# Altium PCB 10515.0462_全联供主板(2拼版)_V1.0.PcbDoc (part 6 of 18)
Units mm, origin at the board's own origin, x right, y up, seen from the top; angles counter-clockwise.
Board outline 282 x 198 mm, 2 copper layers (Top Layer, Bottom Layer); 716 components, 0 nets, 2364 pads, 1800 vias.
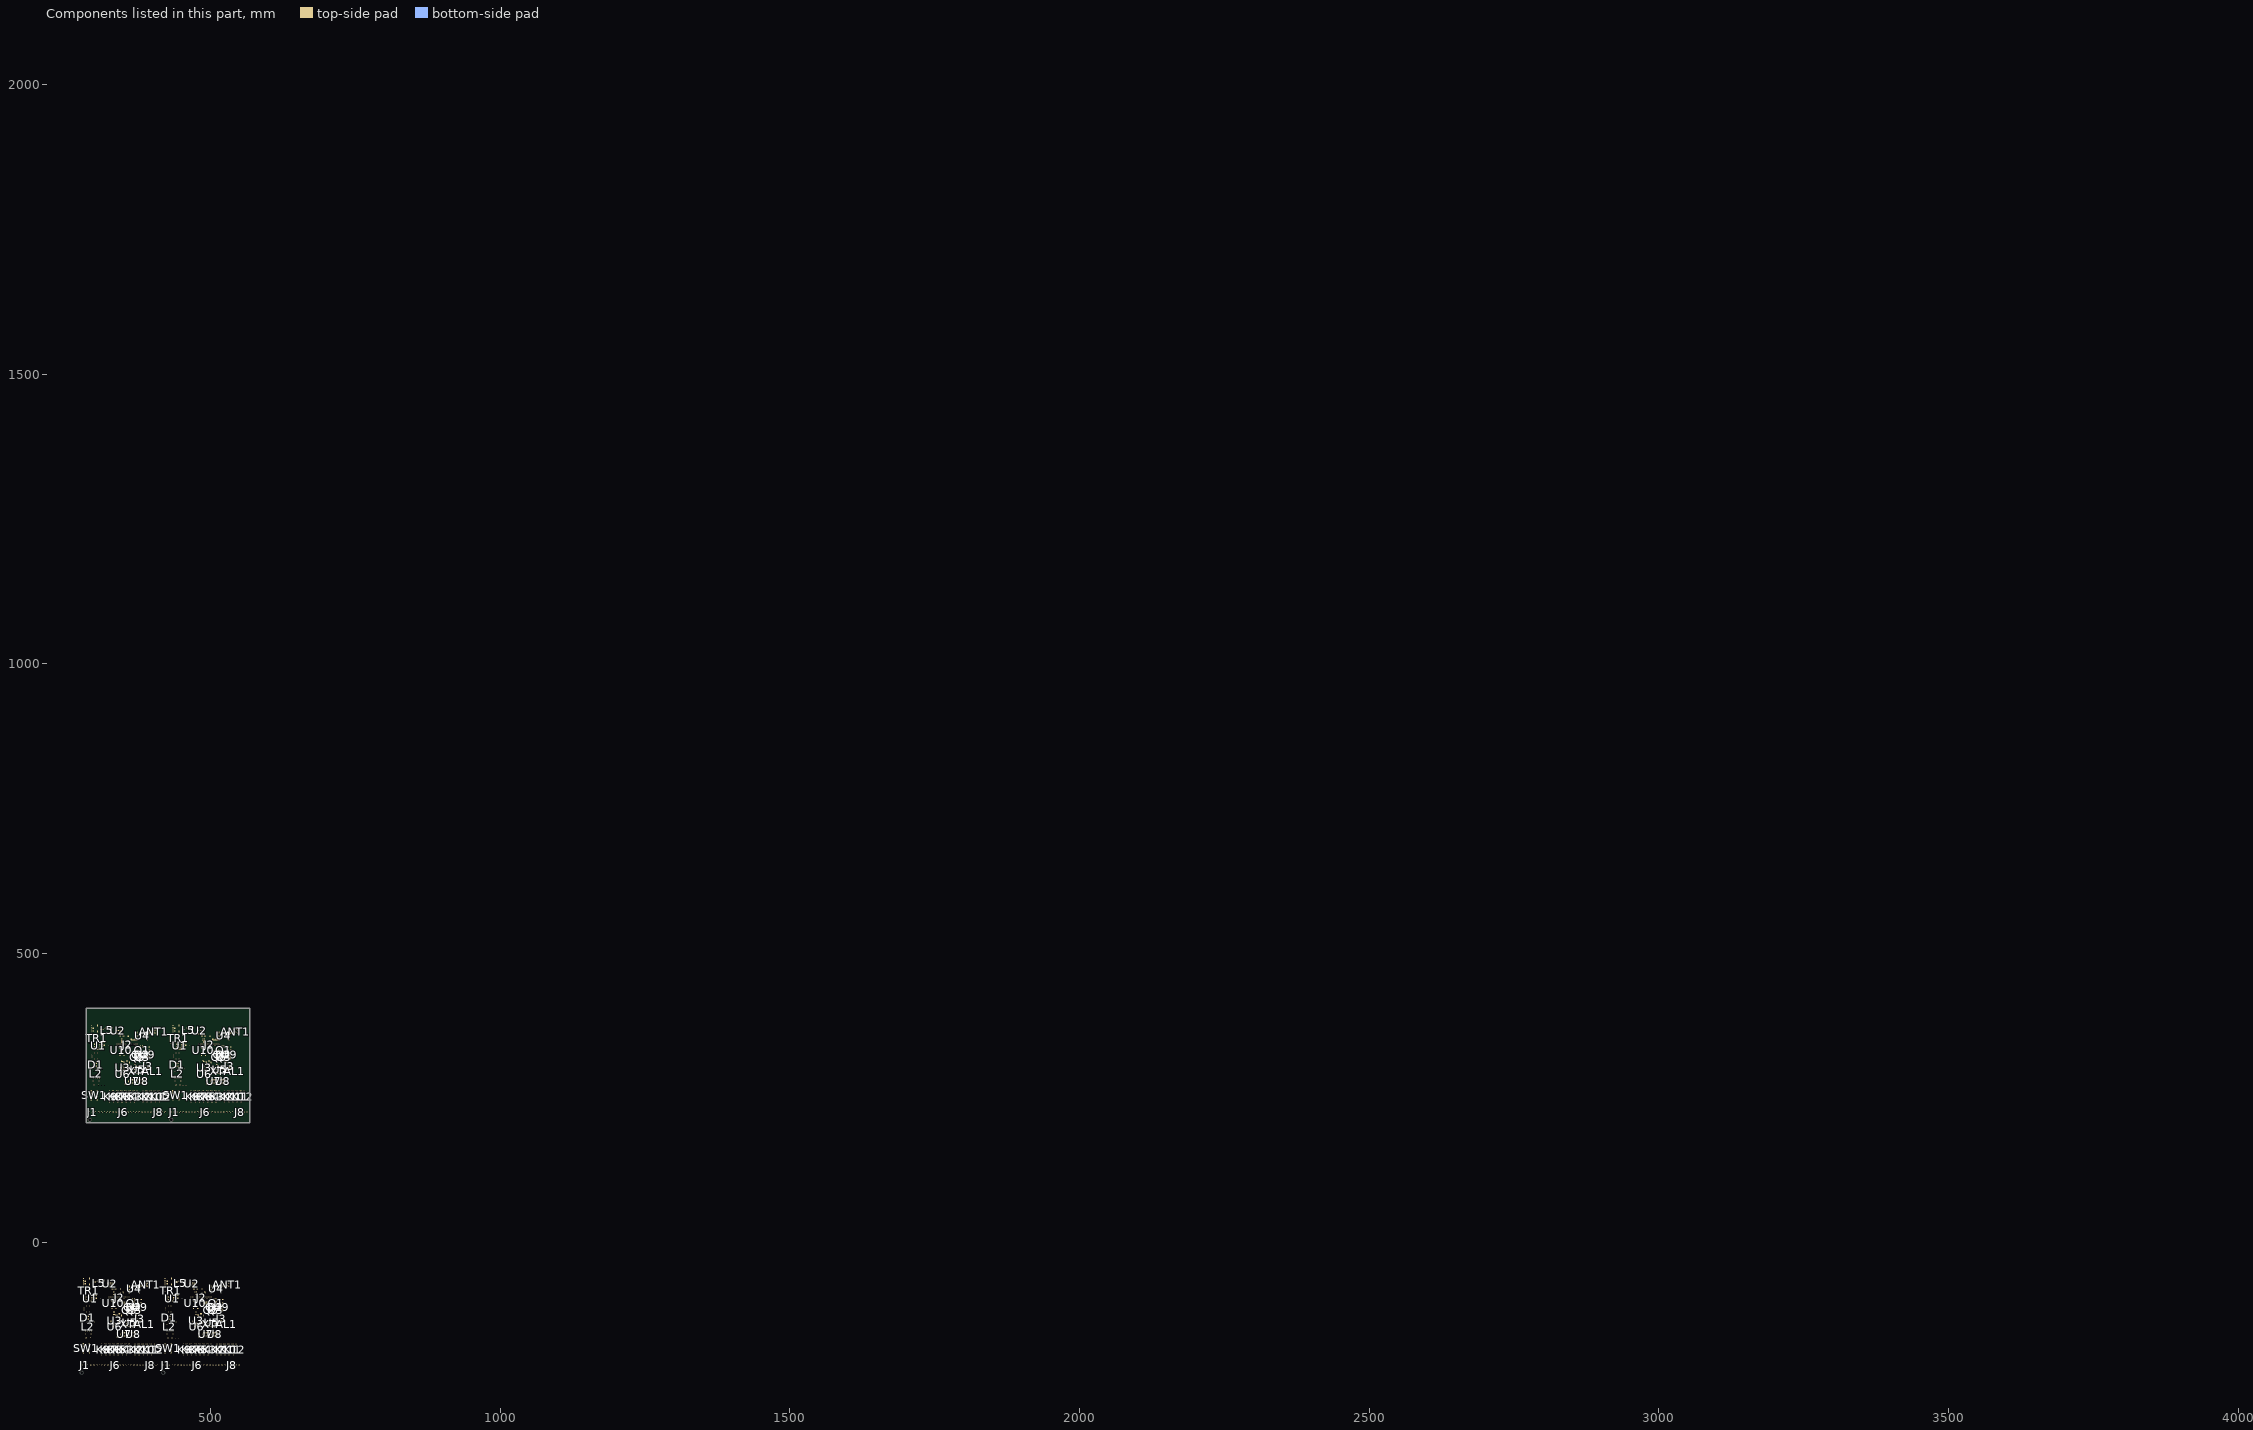
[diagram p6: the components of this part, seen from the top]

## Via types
v1: diameter 0.7, hole 0.4, Top Layer to Bottom Layer, tented both sides, 1800 vias

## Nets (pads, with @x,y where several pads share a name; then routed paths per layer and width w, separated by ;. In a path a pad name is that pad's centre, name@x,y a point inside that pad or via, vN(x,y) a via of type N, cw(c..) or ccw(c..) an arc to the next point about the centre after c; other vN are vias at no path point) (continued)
copper on no net: (continued)
  Top Layer w0.45: 289.059,-97.823 289.059,-97.562 ; 289.059,-95.283 289.059,-94.895 ; 290.415,-99.768 ccw(c290.263,-99.478) 290.59,-99.478 ; 290.59,-100.099 290.59,-99.478 ; 290.677,-100.099 cw(c292.386,-100.099) 291.178,-98.891 ; 290.765,-99.768 cw(c290.917,-99.478) 290.59,-99.478 ; 291.127,-100.099 cw(c293.923,-100.099) 291.946,-98.123 ; 292.576,-99.834 ccw(c291.851,-99.11) 292.876,-99.11 ; 292.876,-99.972 292.876,-96.049 293.642,-95.283 295.155,-95.283 297.071,-95.283 297.448,-94.906 297.448,-93.763 298.464,-92.747 ; 292.876,-99.279 ccw(c293.662,-99.279) 293.106,-99.834 ; 295.155,-97.823 298.976,-97.823 ; 295.155,-94.013 292.753,-94.013 291.987,-94.779 291.987,-98.081 290.59,-99.478 ; 295.375,-90.056 ccw(c296.32,-89.112) 296.32,-90.447 ; 295.693,-89.738 ccw(c297.406,-88.025) 297.406,-90.447 ; 296.012,-89.42 ccw(c298.492,-86.939) 298.492,-90.447 ; 296.226,-90.447 299.48,-90.447 302.209,-90.447 ; 297.196,-97.823 ccw(c297.196,-95.198) 299.053,-97.054 ; 298.283,-97.823 ccw(c298.283,-96.284) 299.371,-97.372 ; 299.042,-93.001 ccw(c298.464,-93.532) 298.464,-92.747 ; 299.042,-92.494 cw(c298.464,-91.963) 298.464,-92.747 ; 299.053,-90.713 ccw(c298.413,-91.353) 298.413,-90.447 ccw(c298.413,-89.542) 299.053,-90.182 ; 299.48,-92.747 298.464,-92.747 ; 299.632,-90.447 ccw(c299.632,-87.582) 301.658,-89.608 ; 299.907,-90.713 cw(c300.547,-91.353) 300.547,-90.447 cw(c300.547,-89.542) 299.907,-90.182 ; 300.356,-90.447 cw(c300.356,-92.29) 301.658,-90.987 ; 300.494,-90.447 cw(c300.494,-92.639) 302.119,-91.169 ; 300.719,-90.447 ccw(c300.719,-88.668) 301.977,-89.926 ; 301.047,-90.447 ccw(c301.047,-89.355) 301.819,-90.128 ; v1(301.986,-81.687) 303.002,-82.703 304.78,-82.703 ; v1@302.191,-81.892 ccw(c302.621,-81.462) v1@302.621,-82.07 ; 302.494,-80.544 301.859,-80.544 301.605,-80.798 301.605,-82.068 302.24,-82.703 304.78,-82.703 ; 302.688,338.772 302.688,339.033 ; 302.688,341.312 302.688,341.7 ; v1@302.746,-82.195 ccw(c303.354,-82.195) 302.924,-82.625 ; 304.044,336.828 ccw(c303.892,337.117) 304.219,337.117 ccw(c304.545,337.117) 304.393,336.828 ; 304.219,336.496 304.219,337.117 305.616,338.514 305.616,341.816 306.382,342.582 308.784,342.582 ; 304.306,336.496 cw(c306.015,336.496) 304.806,337.705 ; 304.756,336.496 cw(c307.551,336.496) 305.575,338.473 ; 306.205,336.761 ccw(c305.48,337.486) 306.505,337.486 ; 306.505,336.623 306.505,340.546 307.271,341.312 308.784,341.312 310.7,341.312 311.077,341.689 311.077,342.832 312.093,343.848 ; 306.505,337.317 ccw(c307.291,337.317) 306.735,336.761 ; 308.784,338.772 312.605,338.772 ; 309.004,346.539 ccw(c309.948,347.484) 309.948,346.148 ; 309.322,346.857 ccw(c311.035,348.57) 311.035,346.148 ; 309.64,347.176 ccw(c312.121,349.656) 312.121,346.148 ; 309.855,346.148 313.109,346.148 315.838,346.148 ; 310.825,338.772 ccw(c310.825,341.398) 312.682,339.541 ; 311.194,-173.925 ccw(c310.041,-172.772) 311.671,-172.772 ccw(c313.301,-172.772) 312.148,-173.925 ; 311.671,-174.752 311.671,-172.123 314.72,-169.074 346.978,-169.074 347.613,-168.439 347.613,-166.153 347.613,-160.438 ; 311.912,338.772 ccw(c311.912,340.311) 313,339.223 ; 312.671,343.594 ccw(c312.093,343.063) 312.093,343.848 ; 312.671,344.102 cw(c312.093,344.633) 312.093,343.848 ; 312.682,345.883 ccw(c312.041,345.243) 312.041,346.148 ccw(c312.041,347.053) 312.682,346.413 ; 313.109,343.848 312.093,343.848 ; 313.261,346.148 ccw(c313.261,349.013) 315.287,346.987 ; 313.536,345.883 cw(c314.176,345.243) 314.176,346.148 cw(c314.176,347.053) 313.536,346.413 ; 313.985,346.148 cw(c313.985,344.306) 315.287,345.608 ; 314.123,346.148 cw(c314.123,343.956) 315.748,345.426 ; 314.348,346.148 ccw(c314.348,347.927) 315.605,346.669 ; 314.676,346.148 ccw(c314.676,347.24) 315.448,346.468 ; v1(315.615,354.908) 316.631,353.892 318.409,353.892 ; v1@315.82,354.704 ccw(c316.25,355.134) v1@316.25,354.525 ; 316.083,-83.846 314.94,-82.703 304.78,-82.703 ; 316.123,356.051 315.488,356.051 315.234,355.797 315.234,354.527 315.869,353.892 318.409,353.892 ; v1@316.375,354.4 ccw(c316.983,354.4) 316.553,353.97 ; 318.379,-173.925 ccw(c317.227,-172.772) 318.856,-172.772 ccw(c320.486,-172.772) 319.334,-173.925 ; 318.856,-174.752 318.856,-172.05 321.1,-169.806 347.897,-169.806 348.883,-168.82 348.883,-166.534 348.883,-160.438 ; 320.995,-71.781 321.544,-71.781 ; 321.29,-72.035 321.544,-71.781 ; 321.544,-71.831 cw(c322.391,-71.831) 321.932,-71.119 ; 321.63,-67.78 cw(c321.139,-68.272) 321.834,-68.272 ; 321.706,-69.111 ccw(c321.396,-68.802) 321.834,-68.802 ccw(c322.272,-68.802) 321.962,-69.111 ; 321.834,-71.781 321.925,-71.781 ; 321.834,-67.666 321.834,-69.278 322.198,-69.642 324.458,-69.642 ; 321.847,-70.942 324.458,-70.942 ; 321.962,-70.801 ccw(c322.304,-70.459) 322.304,-70.942 ; 321.962,-69.188 ccw(c323.06,-68.09) 323.06,-69.642 ; 321.979,-70.857 ccw(c322.814,-70.225) v1@322.814,-71.273 ; 322.772,-70.942 ccw(c322.772,-70.469) v1@323.107,-70.804 ; v1@323.08,-70.844 cw(c322.433,-70.571) 322.433,-71.273 ; v1(323.195,-70.892) v1@322.814,-71.273 ; v1@323.284,-70.804 ccw(c323.618,-70.469) 323.618,-70.942 ; 323.436,-67.717 v1(324.211,-67.717) ; 323.538,-67.524 ccw(c324.004,-67.058) v1@324.004,-67.717 ; 323.713,-72.76 cw(c323.403,-73.07) 323.841,-73.07 cw(c324.279,-73.07) 323.97,-72.76 ; 323.841,-75.022 ccw(c324.32,-75.022) 324.073,-75.432 ; 323.841,-74.225 ccw(c324.8,-74.225) 324.305,-75.047 ; 323.841,-73.429 ccw(c325.28,-73.429) 324.538,-74.661 ; 324.36,-96.285 cw(c323.93,-97.235) 324.973,-97.235 ; 324.499,-75.475 323.841,-74.818 323.841,-72.632 ccw(c325.76,-72.632) 324.77,-74.276 ; 324.545,-95.875 cw(c324.245,-96.538) 324.973,-96.538 ; 324.822,262.671 ccw(c323.67,263.823) 325.3,263.823 ccw(c326.929,263.823) 325.777,262.671 ; 324.973,-96.188 324.973,-97.181 ; 325.3,261.843 325.3,264.472 328.349,267.521 360.607,267.521 361.242,268.156 361.242,270.442 361.242,276.157 ; 325.474,-96.565 cw(c327.121,-98.212) 327.121,-95.882 ; 325.492,-72.632 326.901,-72.632 ; 325.539,-173.925 ccw(c324.386,-172.772) 326.016,-172.772 ccw(c327.645,-172.772) 326.493,-173.925 ; 325.659,-72.76 cw(c325.968,-73.07) 325.968,-72.632 cw(c325.968,-72.194) 325.659,-72.504 ; 325.804,-96.234 cw(c326.304,-96.735) 326.769,-96.201 ; 325.989,-129.312 324.973,-128.296 324.973,-97.181 ; 326.016,-174.752 326.016,-172.257 327.816,-170.456 349.025,-170.456 350.153,-169.328 350.153,-167.042 350.153,-160.438 ; 326.145,-95.893 cw(c326.622,-96.37) 327.064,-95.861 ; 326.242,-95.797 cw(c327.121,-96.675) 327.121,-95.432 ; 326.243,-95.795 324.973,-97.065 324.973,-97.181 ; 326.387,-72.632 ccw(c326.387,-72.102) 326.761,-72.477 ; 327.243,-136.468 328.848,-136.468 329.123,-136.193 v1(329.672,-136.193) ; 327.243,-134.817 328.786,-134.817 ; 327.371,-136.596 cw(c327.681,-136.906) 327.681,-136.468 cw(c327.681,-136.03) 327.371,-136.34 ; 327.371,-134.945 cw(c327.681,-135.255) 327.681,-134.817 cw(c327.681,-134.379) 327.371,-134.689 ; 328.362,-136.468 ccw(c328.362,-136.006) 328.689,-136.333 ; 328.362,-134.817 ccw(c328.362,-134.355) 328.689,-134.682 ; 328.396,-136.468 cw(c328.396,-136.882) 328.689,-136.589 ; 328.396,-134.817 cw(c328.396,-135.231) 328.689,-134.938 ; v1(328.656,-68.987) 329.412,-68.987 ; 328.849,-136.467 cw(c329.357,-136.975) v1@329.625,-136.309 ; 328.892,-134.923 331.294,-134.923 333.273,-134.923 333.58,-135.229 333.58,-138.086 ; v1@328.899,-68.987 cw(c328.899,-69.7) 329.403,-69.196 ; 328.945,-134.758 ccw(c329.343,-134.36) 329.343,-134.923 ; 328.966,-136.564 cw(c329.672,-137.049) v1(329.672,-136.193) ; 329.329,-145.584 331.364,-145.584 ; 329.448,-144.314 331.364,-144.314 337.46,-144.314 ; 329.452,-132.887 cw(c330.072,-132.887) v1@329.634,-132.448 ; v1@329.634,-132.272 ccw(c329.902,-132.004) 329.902,-132.383 ; 329.661,-92.718 ccw(c329.661,-91.422) 330.578,-92.339 ccw(c331.494,-93.255) 330.198,-93.255 cw(c332.722,-93.255) 330.937,-91.471 ; 329.712,352.749 328.569,353.892 318.409,353.892 ; 329.748,-93.255 cw(c331.185,-93.255) 330.169,-92.239 ; 330.561,-91.466 331.654,-90.373 332.238,-90.373 331.145,-91.466 ; 330.942,-91.466 329.661,-92.747 329.661,-93.255 331.45,-91.466 ; 330.959,-91.068 cw(c332.199,-92.309) 332.199,-90.554 ; 331.294,-136.193 v1(329.672,-136.193) ; 331.294,-133.653 329.463,-133.653 329.452,-133.641 329.452,-132.394 329.463,-132.383 331.294,-132.383 ; 331.364,-146.854 329.456,-146.854 329.325,-146.722 329.325,-143.42 329.702,-143.044 331.364,-143.044 333.258,-143.044 333.516,-142.785 333.516,-141.515 333.516,-140.708 333.736,-140.488 v1(336.403,-140.488) ; 331.381,-90.646 cw(c331.824,-91.089) 332.115,-90.534 ; 331.727,-90.3 cw(c332.199,-90.772) 332.199,-90.104 ; 331.863,-90.748 ccw(c331.488,-90.373) 332.018,-90.373 ; 332.008,262.671 ccw(c330.855,263.823) 332.485,263.823 ccw(c334.115,263.823) 332.962,262.671 ; 332.071,-90.501 ccw(c331.761,-90.811) 331.761,-90.373 ccw(c331.761,-89.935) 332.071,-90.245 ; 332.485,261.843 332.485,264.545 334.729,266.789 361.526,266.789 362.512,267.775 362.512,270.061 362.512,276.157 ; 332.786,-173.851 ccw(c332.253,-173.098) 333.175,-173.098 ; 333.175,-174.752 333.175,-173.098 ; 333.362,-131.053 cw(c333.053,-131.362) 333.491,-131.362 cw(c333.929,-131.362) 333.619,-131.053 ; 333.388,-141.644 cw(c333.078,-141.953) 333.516,-141.953 cw(c333.954,-141.953) 333.644,-141.644 ; 333.388,-141.387 ccw(c333.078,-141.077) 333.516,-141.077 ccw(c333.954,-141.077) 333.644,-141.387 ; 333.451,-137.958 ccw(c333.142,-137.648) 333.58,-137.648 ccw(c334.017,-137.648) 333.708,-137.958 ; v1(333.491,-134.13) 333.491,-131.051 ; 333.565,-173.851 cw(c334.098,-173.098) 333.175,-173.098 ; 334.624,364.814 335.173,364.814 ; 334.919,364.56 335.173,364.814 ; 335.013,-131.053 cw(c334.724,-131.342) 335.133,-131.342 ; 335.039,-141.644 cw(c334.729,-141.953) 335.167,-141.953 cw(c335.605,-141.953) 335.295,-141.644 ; 335.102,-137.958 ccw(c334.793,-137.648) 335.231,-137.648 ccw(c335.668,-137.648) 335.359,-137.958 ; 335.133,-131.383 cw(c335.6,-131.383) 335.27,-131.053 ; 335.133,-131.09 335.133,-131.957 335.559,-132.383 337.39,-132.383 ; 335.173,364.764 cw(c336.019,364.764) 335.561,365.476 ; 335.231,-138.086 335.231,-134.086 335.664,-133.653 337.39,-133.653 339.537,-133.653 339.993,-133.197 ; 335.259,368.815 cw(c334.767,368.323) 335.463,368.323 ; 335.333,-141.644 cw(c335.643,-141.953) 335.643,-141.515 cw(c335.643,-141.077) 335.333,-141.387 ; 335.335,367.484 ccw(c335.025,367.794) 335.463,367.794 ccw(c335.901,367.794) 335.591,367.484 ; 335.463,364.814 335.554,364.814 ; 335.463,368.93 335.463,367.318 335.827,366.953 338.087,366.953 ; 335.476,365.653 338.087,365.653 ; 335.591,365.795 ccw(c335.933,366.137) 335.933,365.653 ; 335.591,367.408 ccw(c336.688,368.505) 336.688,366.953 ; 335.607,365.738 ccw(c336.443,366.37) v1@336.443,365.322 ; 336.401,365.653 ccw(c336.401,366.127) v1@336.735,365.792 ; v1(336.694,-138.112) 340.07,-138.112 344.642,-138.112 ; v1@336.709,365.752 cw(c336.062,366.024) 336.062,365.322 ; v1(336.773,-141.515) 335.167,-141.515 335.167,-142.785 335.425,-143.044 337.46,-143.044 ; v1(336.824,365.703) v1@336.443,365.322 ; v1@336.912,365.792 ccw(c337.247,366.127) 337.247,365.653 ; 337.065,368.878 v1(337.84,368.878) ; 337.167,369.072 ccw(c337.633,369.538) v1@337.633,368.878 ; 337.342,363.835 cw(c337.032,363.525) 337.47,363.525 cw(c337.908,363.525) 337.598,363.835 ; 337.39,-136.193 339.853,-136.193 340.095,-136.435 341.517,-136.435 ; 337.39,-134.923 341.442,-134.923 341.517,-134.848 ; 337.47,361.574 ccw(c337.949,361.574) 337.702,361.163 ; 337.47,362.37 ccw(c338.429,362.37) 337.934,361.549 ; 337.47,363.167 ccw(c338.909,363.167) 338.166,361.934 ; 337.988,340.311 cw(c337.559,339.36) 338.602,339.36 ; 338.128,361.12 337.47,361.778 337.47,363.963 ccw(c339.389,363.963) 338.399,362.32 ; 338.174,340.721 cw(c337.874,340.058) 338.602,340.058 ; 338.547,-133.653 ccw(c338.547,-131.789) 339.865,-133.107 ; 338.602,340.408 338.602,339.414 ; 339.077,-136.193 cw(c339.077,-137.416) 339.942,-136.551 ; 339.103,340.031 cw(c340.75,338.384) 340.75,340.713 ; 339.121,363.963 340.529,363.963 ; 339.167,262.671 ccw(c338.015,263.823) 339.645,263.823 ccw(c341.274,263.823) 340.122,262.671 ; 339.288,363.835 cw(c339.597,363.525) 339.597,363.963 cw(c339.597,364.401) 339.288,364.092 ; 339.433,340.361 cw(c339.933,339.861) 340.397,340.395 ; 339.467,-134.923 ccw(c339.467,-134.36) 339.865,-134.758 ; 339.618,-133.572 cw(c339.993,-133.946) 339.993,-133.416 ; 339.618,307.283 338.602,308.299 338.602,339.414 ; 339.633,-133.653 ccw(c339.633,-132.875) 340.183,-133.425 ; 339.645,261.843 339.645,264.339 341.445,266.139 362.654,266.139 363.782,267.267 363.782,269.553 363.782,276.157 ; 339.774,340.702 cw(c340.251,340.226) 340.693,340.734 ; 339.871,340.799 cw(c340.75,339.92) 340.75,341.163 ; 339.872,340.8 338.602,339.53 338.602,339.414 ; 339.942,-138.24 ccw(c339.632,-138.55) 339.632,-138.112 ccw(c339.632,-137.674) 339.942,-137.984 ; 340.015,363.963 ccw(c340.015,364.493) 340.39,364.119 ; 340.111,-174.417 cw(c341.424,-174.331) 340.493,-173.4 ; 340.121,-134.758 ccw(c340.519,-134.36) 340.519,-134.923 ; 340.198,-138.24 cw(c340.508,-138.55) 340.508,-138.112 cw(c340.508,-137.674) 340.198,-137.984 ; 340.198,-136.551 cw(c340.477,-136.83) 340.477,-136.435 ; 340.198,-136.294 ccw(c340.539,-135.954) 340.539,-136.435 ; 340.335,-174.752 340.335,-173.558 341.898,-171.995 351.169,-171.995 352.693,-170.471 352.693,-168.185 352.693,-160.438 ; 340.56,-174.387 cw(c342.742,-174.244) 341.196,-172.698 ; 340.872,300.128 342.477,300.128 342.752,300.403 v1(343.301,300.403) ; 340.872,301.779 342.415,301.779 ; 340.991,-134.923 ccw(c340.991,-134.36) 341.389,-134.758 ; 341,299.999 cw(c341.31,299.69) 341.31,300.128 cw(c341.31,300.566) 341,300.256 ; 341,301.65 cw(c341.31,301.341) 341.31,301.779 cw(c341.31,302.217) 341,301.907 ; 341.009,-174.358 cw(c344.06,-174.158) 341.898,-171.996 ; 341.351,-136.564 ccw(c341.041,-136.873) 341.041,-136.435 ccw(c341.041,-135.997) 341.351,-136.307 ; 341.517,-133.197 v1(342.447,-133.197) ; 341.645,-133.325 cw(c341.955,-133.635) 341.955,-133.197 cw(c341.955,-132.759) 341.645,-133.069 ; 341.991,300.128 ccw(c341.991,300.59) 342.318,300.263 ; 341.991,301.779 ccw(c341.991,302.241) 342.318,301.914 ; 342.025,300.128 cw(c342.025,299.714) 342.318,300.006 ; 342.025,301.779 cw(c342.025,301.365) 342.318,301.657 ; v1(342.285,367.608) 343.041,367.608 ; 342.478,300.128 cw(c342.986,299.62) v1@343.254,300.287 ; 342.52,301.673 344.923,301.673 346.902,301.673 347.208,301.367 347.208,298.509 ; v1@342.528,367.608 cw(c342.528,366.896) 343.032,367.4 ; 342.574,301.838 ccw(c342.972,302.236) 342.972,301.673 ; 342.595,300.032 cw(c343.301,299.546) v1(343.301,300.403) ; 342.958,291.012 344.993,291.012 ; 343.077,292.282 344.993,292.282 351.089,292.282 ; 343.081,303.709 cw(c343.7,303.709) v1@343.262,304.147 ; 343.168,-136.435 346.102,-136.435 ; v1@343.262,304.324 ccw(c343.53,304.592) 343.53,304.213 ; 343.29,343.877 ccw(c343.29,345.174) 344.206,344.257 ccw(c345.123,343.34) 343.827,343.34 cw(c346.35,343.34) 344.566,345.125 ; 343.334,-136.564 cw(c343.644,-136.873) 343.644,-136.435 cw(c343.644,-135.997) 343.334,-136.307 ; 343.377,343.34 cw(c344.814,343.34) 343.798,344.356 ; 343.475,-80.259 cw(c342.152,-81.582) 344.023,-81.582 cw(c345.894,-81.582) 344.571,-80.259 ; 344.023,-86.711 344.628,-86.107 ; 344.023,-79.711 344.023,-83.719 344.468,-84.163 344.76,-84.456 349.661,-84.456 349.737,-84.379 359.054,-84.379 359.303,-84.13 ; 344.173,-136.435 ccw(c344.173,-135.954) 344.514,-136.294 ; 344.19,345.129 345.283,346.222 345.866,346.222 344.773,345.129 ; 344.235,-136.435 cw(c344.235,-136.83) 344.514,-136.551 ; 344.488,-158.635 345.683,-158.635 ; 344.514,-138.24 ccw(c344.204,-138.55) 344.204,-138.112 ccw(c344.204,-137.674) 344.514,-137.984 ; 344.571,345.129 343.29,343.848 343.29,343.34 345.079,345.129 ; 344.588,345.527 cw(c345.828,344.287) 345.828,346.041 ; 344.616,-158.763 cw(c344.926,-159.073) 344.926,-158.635 cw(c344.926,-158.197) 344.616,-158.507 ; 344.616,-157.112 cw(c344.926,-157.422) 344.926,-156.984 cw(c344.926,-156.546) 344.616,-156.856 ; 344.77,-136.551 cw(c345.049,-136.83) 345.049,-136.435 ; 344.77,-136.294 ccw(c345.111,-135.954) 345.111,-136.435 ; 344.923,300.403 v1(343.301,300.403) ; 344.923,302.943 343.092,302.943 343.081,302.954 343.081,304.202 343.092,304.213 344.923,304.213 ; 344.993,289.742 343.085,289.742 342.954,289.873 342.954,293.175 343.331,293.552 344.993,293.552 346.887,293.552 347.145,293.81 347.145,295.08 347.145,295.887 347.365,296.107 v1(350.032,296.107) ; 345.01,345.95 cw(c345.453,345.507) 345.744,346.062 ; 345.356,346.295 cw(c345.828,345.823) 345.828,346.491 ; 345.492,345.848 ccw(c345.117,346.222) 345.647,346.222 ; 345.7,346.094 ccw(c345.39,345.785) 345.39,346.222 ccw(c345.39,346.66) 345.7,346.351 ; 345.852,-158.804 cw(c344.967,-159.688) 346.218,-159.688 ; 345.986,-136.564 ccw(c345.676,-136.873) 345.676,-136.435 ccw(c345.676,-135.997) 345.986,-136.307 ; 346.343,-160.438 346.343,-159.295 345.683,-158.635 ; 346.343,-159.919 346.309,-159.885 346.309,-158.635 ; 346.343,-154.85 346.343,-156.236 ; 346.415,262.745 ccw(c345.882,263.498) 346.804,263.498 ; 346.463,-105.32 346.465,-105.318 ; 346.69,-156.984 346.343,-156.637 346.343,-156.236 ; 346.804,261.843 346.804,263.498 ; 346.991,305.543 cw(c346.681,305.233) 347.119,305.233 cw(c347.557,305.233) 347.248,305.543 ; 347.017,294.952 cw(c346.707,294.642) 347.145,294.642 cw(c347.583,294.642) 347.273,294.952 ; 347.017,295.208 ccw(c346.707,295.518) 347.145,295.518 ccw(c347.583,295.518) 347.273,295.208 ; 347.071,-86.107 351.034,-86.107 351.161,-85.98 ; 347.08,298.637 ccw(c346.77,298.947) 347.208,298.947 ccw(c347.646,298.947) 347.337,298.637 ; v1(347.119,302.466) 347.119,305.544 ; 347.194,262.745 cw(c347.726,263.498) 346.804,263.498 ; 347.495,-174.752 347.495,-173.765 348.502,-172.757 352.566,-172.757 353.963,-171.36 353.963,-169.074 353.963,-160.438 ; 347.71,-174.336 cw(c348.715,-174.03) 347.972,-173.288 ; 347.836,-86.107 ccw(c347.836,-85.644) 348.163,-85.971 ; 347.836,-84.456 ccw(c347.836,-83.993) 348.163,-84.32 ; 347.871,-86.107 cw(c347.871,-86.52) 348.163,-86.228 ; 347.871,-84.456 cw(c347.871,-84.869) 348.163,-84.577 ; 348.14,-174.205 cw(c349.527,-173.782) 348.502,-172.757 ; 348.419,-86.228 cw(c348.712,-86.52) 348.712,-86.107 ; 348.419,-85.971 ccw(c348.746,-85.644) 348.746,-86.107 ; 348.419,-84.577 cw(c348.712,-84.869) 348.712,-84.456 ; 348.419,-84.32 ccw(c348.746,-83.993) 348.746,-84.456 ; 348.642,305.543 cw(c348.353,305.254) 348.762,305.254 ; 348.668,294.952 cw(c348.358,294.642) 348.796,294.642 cw(c349.234,294.642) 348.924,294.952 ; 348.731,298.637 ccw(c348.421,298.947) 348.859,298.947 ccw(c349.297,298.947) 348.988,298.637 ; 348.762,305.213 cw(c349.229,305.213) 348.899,305.543 ; 348.762,305.505 348.762,304.639 349.188,304.213 351.019,304.213 ; 348.859,298.509 348.859,302.51 349.293,302.943 351.019,302.943 353.166,302.943 353.622,303.399 ; 348.962,294.952 cw(c349.272,294.642) 349.272,295.08 cw(c349.272,295.518) 348.962,295.208 ; 349.533,-86.235 ccw(c349.223,-86.545) 349.223,-86.107 ccw(c349.223,-85.669) 349.533,-85.978 ; 349.533,-84.584 ccw(c349.223,-84.894) 349.223,-84.456 ccw(c349.223,-84.018) 349.533,-84.327 ; 349.789,-86.235 cw(c350.099,-86.545) 350.099,-86.107 cw(c350.099,-85.669) 349.789,-85.978 ; 349.789,-84.546 cw(c350.191,-84.947) 350.191,-84.379 ; 349.899,-143.143 349.901,-143.141 350.754,-143.141 351.727,-143.141 ; 350.027,-143.272 cw(c350.342,-143.587) 350.342,-143.141 ; 350.027,-143.015 ccw(c350.331,-142.711) 350.331,-143.141 ; v1(350.323,298.484) 353.699,298.484 358.271,298.484 ; 350.378,-86.107 ccw(c350.378,-85.235) 350.994,-85.851 ; v1(350.401,295.08) 348.796,295.08 348.796,293.81 349.054,293.552 351.089,293.552 ; v1(350.895,-141.49) 351.657,-141.49 ; 351.019,300.403 353.481,300.403 353.724,300.16 355.146,300.16 ; 351.019,301.673 355.071,301.673 355.146,301.748 ; 351.423,-160.438 351.423,-167.677 351.423,-169.963 350.28,-171.106 335.167,-171.106 333.175,-173.098 ; 351.599,-143.269 ccw(c351.289,-143.579) 351.289,-143.141 ccw(c351.289,-142.703) 351.599,-143.013 ; 351.599,-141.618 ccw(c351.289,-141.928) 351.289,-141.49 ccw(c351.289,-141.052) 351.599,-141.362 ; 351.727,-141.49 352.419,-141.49 v1@352.888,-141.021 ; 351.855,-141.618 cw(c352.165,-141.928) 352.165,-141.49 cw(c352.165,-141.052) 351.855,-141.362 ; 352.141,-96.175 cw(c351.225,-97.092) 352.521,-97.092 cw(c353.817,-97.092) 352.901,-96.175 ; v1@352.151,-133.126 v1@352.151,-127.28 ; 352.151,-127.888 cw(c352.886,-127.888) v1@352.367,-127.368 ; 352.176,302.943 ccw(c352.176,304.807) 353.494,303.489 ; 352.521,-95.795 352.521,-98.821 352.913,-99.213 356.977,-99.213 357.298,-99.534 357.298,-107.281 357.624,-107.606 359.15,-107.606 359.15,-107.65 ; 352.546,-141.363 ccw(c351.96,-140.777) v1@352.788,-140.747 ; 352.705,300.403 cw(c352.705,299.179) 353.571,300.045 ; 352.812,-85.98 352.962,-86.13 359.303,-86.13 ; 352.978,-85.851 ccw(c353.651,-85.179) 353.651,-86.13 ; 353.095,301.673 ccw(c353.095,302.236) 353.494,301.838 ; 353.247,303.024 cw(c353.622,302.649) 353.622,303.179 ; 353.262,302.943 ccw(c353.262,303.72) 353.812,303.171 ; 353.448,-105.32 353.448,-105.318 ; 353.571,298.355 ccw(c353.261,298.046) 353.261,298.484 ccw(c353.261,298.922) 353.571,298.612 ; 353.739,262.179 cw(c355.053,262.265) 354.122,263.195 ; 353.75,301.838 ccw(c354.148,302.236) 354.148,301.673 ; 353.801,-86.13 ccw(c353.801,-85.482) 354.259,-85.94 ; 353.827,298.355 cw(c354.137,298.046) 354.137,298.484 cw(c354.137,298.922) 353.827,298.612 ; 353.827,300.045 cw(c354.106,299.765) 354.106,300.16 ; 353.827,300.301 ccw(c354.167,300.641) 354.167,300.16 ; 353.964,261.843 353.964,263.037 355.527,264.6 364.798,264.6 366.322,266.124 366.322,268.41 366.322,276.157 ; 354.12,-173.925 ccw(c351.432,-171.237) 355.233,-171.237 ; 354.188,262.208 cw(c356.371,262.351) 354.824,263.898 ; 354.259,-84.508 ccw(c353.949,-84.817) 353.949,-84.379 ccw(c353.949,-83.941) 354.259,-84.251 ; 354.438,-174.243 ccw(c352.518,-172.323) 355.233,-172.323 ; 354.515,-85.94 ccw(c354.974,-85.482) 354.974,-86.13 ; 354.515,-84.508 cw(c354.825,-84.817) 354.825,-84.379 cw(c354.825,-83.941) 354.515,-84.251 ; 354.619,301.673 ccw(c354.619,302.236) 355.018,301.838 ; 354.637,262.238 cw(c357.689,262.437) 355.527,264.6 ; 354.756,-174.561 ccw(c353.605,-173.41) 355.233,-173.41 ; 354.931,-128.218 ccw(c354.591,-127.877) 355.072,-127.877 ; 354.965,-129.626 ccw(c354.645,-129.306) 355.098,-129.306 ; 354.969,-128.474 cw(c354.66,-128.784) 355.098,-128.784 cw(c355.535,-128.784) 355.226,-128.474 ; 354.979,300.032 ccw(c354.67,299.722) 354.67,300.16 ccw(c354.67,300.598) 354.979,300.288 ; 355.072,-128.321 v1(355.072,-127.28) ; 355.072,-127.939 ccw(c355.467,-127.939) 355.188,-128.218 ; 355.098,-129.721 355.098,-128.346 ; 355.098,-129.327 ccw(c355.521,-129.327) 355.222,-129.626 ; 355.099,-103.669 355.11,-103.658 v1(355.961,-103.658) ; 355.101,-101.941 v1(355.945,-101.941) ; 355.146,303.399 v1(356.076,303.399) ; 355.198,-86.13 ccw(c355.198,-85.482) 355.656,-85.94 ; 355.233,-171.83 355.233,-171.222 ; 355.233,-160.438 355.233,-171.222 ; 355.265,-103.798 cw(c355.603,-104.135) 355.603,-103.658 ; 355.265,-103.541 ccw(c355.548,-103.259) 355.548,-103.658 ; 355.268,-102.07 cw(c355.577,-102.379) 355.577,-101.941 cw(c355.577,-101.503) 355.268,-101.813 ; 355.274,303.27 cw(c355.584,302.961) 355.584,303.399 cw(c355.584,303.837) 355.274,303.527 ; 355.503,-116.209 355.551,-116.162 ; 355.656,-84.508 ccw(c355.346,-84.817) 355.346,-84.379 ccw(c355.346,-83.941) 355.656,-84.251 ; 355.912,-85.94 ccw(c356.371,-85.482) 356.371,-86.13 ; 355.912,-84.508 cw(c356.222,-84.817) 356.222,-84.379 cw(c356.222,-83.941) 355.912,-84.251 ; 356.595,-86.13 ccw(c356.595,-85.482) 357.053,-85.94 ; 356.616,-129.626 ccw(c356.296,-129.306) 356.749,-129.306 ; 356.62,-128.474 cw(c356.311,-128.784) 356.749,-128.784 cw(c357.186,-128.784) 356.877,-128.474 ; 356.749,-129.721 356.749,-128.346 356.985,-128.11 v1(357.612,-128.11) ccw(c357.612,-128.953) 356.933,-128.453 ; 356.749,-129.327 ccw(c357.172,-129.327) 356.873,-129.626 ; 356.797,300.16 359.73,300.16 ; 356.963,300.032 cw(c357.273,299.722) 357.273,300.16 cw(c357.273,300.598) 356.963,300.288 ; 357.053,-84.508 ccw(c356.743,-84.817) 356.743,-84.379 ccw(c356.743,-83.941) 357.053,-84.251 ; 357.104,356.336 cw(c355.781,355.013) 357.652,355.013 cw(c359.523,355.013) 358.2,356.336 ; 357.309,-85.94 ccw(c357.768,-85.482) 357.768,-86.13 ; 357.309,-84.508 cw(c357.619,-84.817) 357.619,-84.379 cw(c357.619,-83.941) 357.309,-84.251 ; 357.587,-84.379 ccw(c357.587,-82.864) 358.659,-83.936 ; 357.652,349.884 358.256,350.489 ; 357.652,356.884 357.652,352.876 358.096,352.432 358.388,352.14 363.29,352.14 363.366,352.216 372.682,352.216 372.932,352.465 ; 357.802,300.16 ccw(c357.802,300.641) 358.143,300.301 ; 357.863,300.16 cw(c357.863,299.765) 358.143,300.045 ; 358.117,277.96 359.311,277.96 ; 358.143,298.355 ccw(c357.833,298.046) 357.833,298.484 ccw(c357.833,298.922) 358.143,298.612 ; 358.245,277.832 cw(c358.555,277.523) 358.555,277.96 cw(c358.555,278.398) 358.245,278.089 ; 358.245,279.483 cw(c358.555,279.174) 358.555,279.611 cw(c358.555,280.049) 358.245,279.74 ; 358.399,300.045 cw(c358.678,299.765) 358.678,300.16 ; 358.399,300.301 ccw(c358.739,300.641) 358.739,300.16 ; 358.659,-86.324 ccw(c358.189,-86.794) 358.189,-86.13 ccw(c358.189,-85.466) 358.659,-85.936 ; 358.779,-107.978 ccw(c357.883,-108.874) 357.883,-107.606 ccw(c357.883,-106.339) 358.779,-107.235 ; 358.893,-114.591 358.998,-114.591 359.131,-114.459 ; 359.48,277.791 cw(c358.596,276.907) 359.847,276.907 ; 359.615,300.032 ccw(c359.305,299.722) 359.305,300.16 ccw(c359.305,300.598) 359.615,300.288 ; 359.854,-158.763 ccw(c359.544,-159.073) 359.544,-158.635 ccw(c359.544,-158.197) 359.854,-158.507 ; 359.854,-157.112 ccw(c359.544,-157.422) 359.544,-156.984 ccw(c359.544,-156.546) 359.854,-156.856 ; 359.972,276.157 359.972,277.3 359.311,277.96 ; 359.972,276.676 359.938,276.71 359.938,277.96 ; 359.972,281.745 359.972,280.359 ; 360.092,331.275 360.094,331.277 ; 360.11,-157.112 cw(c360.42,-157.422) 360.42,-156.984 cw(c360.42,-156.546) 360.11,-156.856 ; 360.319,279.611 359.972,279.959 359.972,280.359 ; 360.7,350.489 364.662,350.489 364.789,350.616 ; 360.758,-112.781 360.78,-112.803 ; 361.124,261.843 361.124,262.831 362.131,263.838 366.195,263.838 367.592,265.235 367.592,267.521 367.592,276.157 ; 361.129,-158.587 cw(c360.028,-159.688) 361.585,-159.688 ; 361.339,262.259 cw(c362.343,262.565) 361.601,263.308 ; 361.465,350.489 ccw(c361.465,350.951) 361.792,350.624 ; 361.465,352.14 ccw(c361.465,352.602) 361.792,352.275 ; 361.499,350.489 cw(c361.499,350.076) 361.792,350.368 ; 361.499,352.14 cw(c361.499,351.727) 361.792,352.019 ; 361.7,-159.688 360.646,-158.635 360.406,-158.635 ; 361.71,-160.565 361.71,-160.438 361.71,-159.168 361.177,-158.635 360.406,-158.635 ; 361.71,-156.236 360.962,-156.984 360.787,-156.984 ; 361.71,-154.977 361.71,-156.628 ; 361.769,262.39 cw(c363.156,262.813) 362.131,263.838 ; 362.048,350.368 cw(c362.34,350.076) 362.34,350.489 ; 362.048,350.624 ccw(c362.375,350.951) 362.375,350.489 ; 362.048,352.019 cw(c362.34,351.727) 362.34,352.14 ; 362.048,352.275 ccw(c362.375,352.602) 362.375,352.14 ; v1(362.692,-117.755) 362.692,-116.975 362.917,-116.75 362.917,-116.052 363.234,-115.734 364.377,-115.734 364.568,-115.544 364.568,-114.591 ; v1@362.692,-117.638 cw(c363.766,-117.638) 363.007,-116.879 ; 362.725,-150.127 cw(c362.415,-150.437) 362.853,-150.437 cw(c363.291,-150.437) 362.981,-150.127 ; 362.788,-116.622 ccw(c362.479,-116.312) 362.917,-116.312 ccw(c363.354,-116.312) 363.045,-116.622 ; v1(362.853,-150.913) 362.853,-149.961 ; 362.917,-119.117 362.917,-118.909 ; 362.98,-160.565 362.98,-169.582 362.98,-171.868 363.488,-172.376 368.822,-172.376 369.456,-173.01 ; 363.162,350.361 ccw(c362.852,350.051) 362.852,350.489 ccw(c362.852,350.927) 363.162,350.617 ; 363.162,352.012 ccw(c362.852,351.702) 362.852,352.14 ccw(c362.852,352.578) 363.162,352.268 ; 363.418,350.361 cw(c363.728,350.051) 363.728,350.489 cw(c363.728,350.927) 363.418,350.617 ; 363.418,352.05 cw(c363.82,351.648) 363.82,352.216 ; 363.528,293.452 363.53,293.454 364.383,293.454 365.356,293.454 ; 363.656,293.324 cw(c363.971,293.009) 363.971,293.454 ; 363.656,293.58 ccw(c363.96,293.885) 363.96,293.454 ; 364.007,350.489 ccw(c364.007,351.36) 364.623,350.744 ; 364.225,-146.168 cw(c363.937,-146.465) 364.352,-146.465 ; 364.25,-160.565 364.25,-168.932 364.25,-171.218 364.758,-171.726 375.411,-171.726 376.568,-172.883 ; 364.352,-146.467 cw(c364.701,-146.467) 364.496,-146.184 ; 364.352,-146.037 364.352,-146.465 ; 364.439,-114.72 cw(c364.13,-115.029) 364.568,-115.029 cw(c365.005,-115.029) 364.696,-114.72 ; 364.478,-146.168 ccw(c364.766,-146.465) 364.352,-146.465 ; v1(364.524,295.105) 365.286,295.105 ; 364.571,-146.042 ccw(c366.033,-146.079) v1@364.999,-147.113 ; 364.803,-112.969 cw(c364.803,-113.959) 365.503,-113.259 ; 364.803,-112.559 v1@365.994,-113.751 ; 365.052,276.157 365.052,268.918 365.052,266.632 363.909,265.489 348.796,265.489 346.804,263.498 ; v1(365.105,-144.425) 366.003,-145.322 366.003,-146.037 ; 365.15,-112.623 ccw(c365.833,-112.623) 365.35,-113.106 ; 365.228,293.326 ccw(c364.918,293.017) 364.918,293.454 ccw(c364.918,293.892) 365.228,293.583 ; 365.228,294.977 ccw(c364.918,294.668) 364.918,295.105 ccw(c364.918,295.543) 365.228,295.234 ; v1(365.232,-147.346) 364.352,-146.465 ; v1(365.232,-120.041) 370.058,-120.041 370.727,-119.372 v1(370.727,-117.12) 370.727,-116.179 ; 365.356,295.105 366.048,295.105 v1@366.516,295.574 ; 365.484,294.977 cw(c365.794,294.668) 365.794,295.105 cw(c365.794,295.543) 365.484,295.234 ; 365.52,-160.565 365.52,-168.282 365.52,-170.568 366.028,-171.076 382,-171.076 383.687,-172.763 ; 365.77,340.42 cw(c364.853,339.504) 366.15,339.504 cw(c367.446,339.504) 366.529,340.42 ; v1@365.78,303.469 v1@365.78,309.315 ; 365.78,308.707 cw(c366.515,308.707) v1@365.995,309.227 ; 365.846,-113.602 cw(c365.517,-113.931) v1@365.982,-113.931 ; 365.874,-145.909 ccw(c365.565,-145.599) 366.003,-145.599 ccw(c366.441,-145.599) 366.131,-145.909 ; 366.15,340.8 366.15,337.775 366.542,337.382 370.606,337.382 370.927,337.061 370.927,329.314 371.252,328.989 372.779,328.989 372.779,328.945 ; 366.175,295.232 ccw(c365.589,295.818) v1@366.417,295.849 ; 366.44,350.616 366.591,350.465 372.932,350.465 ; 366.607,350.744 ccw(c367.279,351.417) 367.279,350.465 ; 366.79,-160.565 366.79,-167.505 366.79,-169.791 367.425,-170.426 389.71,-170.426 390.799,-171.516 390.799,-174.625 ; 367.044,-117.131 367.044,-117.449 368.505,-118.909 ; 367.077,331.275 367.077,331.277 ; 367.391,-117.195 ccw(c368.84,-117.195) 367.815,-118.22 ; 367.429,350.465 ccw(c367.429,351.113) 367.888,350.655 ; 367.748,262.671 ccw(c365.061,265.358) 368.862,265.358 ; 367.888,352.088 ccw(c367.578,351.778) 367.578,352.216 ccw(c367.578,352.654) 367.888,352.344 ; 368.044,-114.631 368.148,-114.528 ; 368.044,-110.469 cw(c368.044,-111.459) 368.744,-110.759 cw(c369.444,-110.059) 368.454,-110.059 ; 368.044,-110.059 369.263,-111.278 370.41,-111.278 ; 368.06,-160.565 368.06,-166.661 368.06,-168.947 368.889,-169.776 396.426,-169.776 398.038,-171.389 398.038,-174.625 ; 368.067,262.353 ccw(c366.147,264.272) 368.862,264.272 ; 368.13,-118.535 cw(c367.755,-118.909) 368.285,-118.909 ; 368.144,350.655 ccw(c368.602,351.113) 368.602,350.465 ; 368.144,352.088 cw(c368.454,351.778) 368.454,352.216 cw(c368.454,352.654) 368.144,352.344 ; 368.3,-98.197 375.011,-98.197 376.916,-98.197 ; 368.3,-95.657 379.202,-95.657 379.837,-96.292 379.837,-97.943 ; 368.385,262.034 ccw(c367.234,263.186) 368.862,263.186 ; 368.56,308.378 ccw(c368.22,308.718) 368.701,308.718 ; 368.594,306.969 ccw(c368.274,307.289) 368.726,307.289 ; 368.598,308.121 cw(c368.288,307.812) 368.726,307.812 cw(c369.164,307.812) 368.855,308.121 ; 368.671,-98.568 cw(c369.567,-99.464) 369.567,-98.197 cw(c369.567,-96.93) 368.671,-97.826 ; 368.671,-96.028 cw(c369.567,-96.924) 369.567,-95.657 cw(c369.567,-94.39) 368.671,-95.286 ; 368.701,308.275 v1(368.701,309.315) ; 368.701,308.657 ccw(c369.095,308.657) 368.816,308.378 ; 368.726,306.875 368.726,308.249 ; 368.726,307.269 ccw(c369.15,307.269) 368.85,306.969 ; 368.728,332.926 368.739,332.937 v1(369.59,332.937) ; 368.73,334.654 v1(369.574,334.654) ; 368.826,350.465 ccw(c368.826,351.113) 369.285,350.655 ; 368.862,264.765 368.862,265.373 ; 368.862,276.157 368.862,265.373 ; 368.894,332.798 cw(c369.231,332.461) 369.231,332.937 ; 368.894,333.054 ccw(c369.176,333.336) 369.176,332.937 ; 368.897,334.526 cw(c369.206,334.216) 369.206,334.654 cw(c369.206,335.092) 368.897,334.782 ; 368.994,-112.559 368.994,-113.135 369.169,-113.31 v1(369.931,-113.31) ; 369.08,-173.714 ccw(c368.609,-173.01) 369.456,-173.01 ; 369.132,320.386 369.179,320.434 ; 369.169,-103.306 cw(c369.169,-104.296) 369.869,-103.596 ; 369.169,-102.896 370.727,-104.454 370.727,-109.944 ; 369.28,-133.286 v1@369.28,-127.28 ; 369.28,-132.503 ccw(c370.152,-132.503) 369.535,-133.119 ; 369.285,352.088 ccw(c368.975,351.778) 368.975,352.216 ccw(c368.975,352.654) 369.285,352.344 ; 369.456,-174.625 369.456,-173.01 ; 369.516,-102.959 ccw(c370.199,-102.959) 369.716,-103.443 ; 369.541,350.655 ccw(c369.999,351.113) 369.999,350.465 ; 369.541,352.088 cw(c369.851,351.778) 369.851,352.216 cw(c369.851,352.654) 369.541,352.344 ; 369.615,-111.278 cw(c369.615,-112.67) 370.599,-111.686 ; 369.832,-173.714 cw(c370.303,-173.01) 369.456,-173.01 ; 370.223,350.465 ccw(c370.223,351.113) 370.682,350.655 ; 370.245,306.969 ccw(c369.925,307.289) 370.377,307.289 ; 370.249,308.121 cw(c369.939,307.812) 370.377,307.812 cw(c370.815,307.812) 370.506,308.121 ; 370.377,306.875 370.377,308.249 370.614,308.486 v1(371.241,308.486) ccw(c371.241,307.643) 370.562,308.142 ; 370.377,307.269 ccw(c370.801,307.269) 370.501,306.969 ; 370.599,-116.345 cw(c370.289,-116.655) 370.727,-116.655 cw(c371.165,-116.655) 370.855,-116.345 ; 370.599,-109.778 ccw(c370.289,-109.468) 370.727,-109.468 ccw(c371.165,-109.468) 370.855,-109.778 ; 370.682,352.088 ccw(c370.372,351.778) 370.372,352.216 ccw(c370.372,352.654) 370.682,352.344 ; 370.938,350.655 ccw(c371.396,351.113) 371.396,350.465 ; 370.938,352.088 cw(c371.248,351.778) 371.248,352.216 cw(c371.248,352.654) 370.938,352.344 ; 371.216,352.216 ccw(c371.216,353.731) 372.287,352.66 ; 371.362,-139.293 372.979,-139.293 373.37,-138.902 373.37,-137.463 373.82,-137.013 ; 371.49,-139.421 cw(c371.8,-139.731) 371.8,-139.293 cw(c371.8,-138.855) 371.49,-139.165 ; 371.884,-139.293 ccw(c371.884,-137.541) 373.123,-138.78 ; 372.287,350.271 ccw(c371.818,349.802) 371.818,350.465 ccw(c371.818,351.129) 372.287,350.66 ; 372.408,328.618 ccw(c371.512,327.722) 371.512,328.989 ccw(c371.512,330.257) 372.408,329.36 ; 372.522,322.004 372.627,322.004 372.76,322.137 ; 372.668,-98.197 ccw(c372.668,-95.727) 374.415,-97.473 ; 373.123,-141.775 cw(c372.157,-142.74) 373.522,-142.74 ; 373.123,-138.53 ccw(c372.525,-137.932) 373.37,-137.932 ccw(c374.215,-137.932) 373.618,-138.53 ; 373.37,-141.402 373.522,-141.555 373.522,-143.27 373.522,-144.057 373.709,-144.243 376.442,-144.243 376.823,-143.862 376.823,-139.633 v1(376.789,-139.599) 376.092,-138.902 ; 373.37,-138.445 cw(c375.213,-138.445) 373.91,-137.142 ; 373.37,-137.623 cw(c373.798,-137.623) 373.786,-137.195 ; 373.37,-137.358 cw(c374.126,-137.358) 373.592,-136.823 ; 373.394,-143.398 cw(c373.084,-143.708) 373.522,-143.708 cw(c373.96,-143.708) 373.651,-143.398 ; 373.394,-143.142 ccw(c373.084,-142.832) 373.522,-142.832 ccw(c373.96,-142.832) 373.651,-143.142 ; 373.445,-137.388 ccw(c373.07,-137.013) 373.6,-137.013 ; 373.483,277.832 ccw(c373.173,277.523) 373.173,277.96 ccw(c373.173,278.398) 373.483,278.089 ; 373.483,279.483 ccw(c373.173,279.174) 373.173,279.611 ccw(c373.173,280.049) 373.483,279.74 ; v1(373.597,-110.406) 374.453,-110.406 ; 373.739,279.483 cw(c374.049,279.174) 374.049,279.611 cw(c374.049,280.049) 373.739,279.74 ; 373.754,-98.197 ccw(c373.754,-96.813) 374.733,-97.792 ; 373.894,-98.197 cw(c373.894,-98.933) 374.415,-98.413 ; 374.122,-133.52 ccw(c373.813,-133.21) 374.251,-133.21 ccw(c374.689,-133.21) 374.379,-133.52 ; 374.251,-133.648 374.251,-132.994 374.63,-132.614 376.662,-132.614 377.515,-131.761 377.515,-131.285 ; 374.325,-110.534 ccw(c374.015,-110.844) 374.015,-110.406 ccw(c374.015,-109.968) 374.325,-110.278 ; 374.386,323.814 374.408,323.792 ; 374.453,-110.279 374.809,-110.635 v1(378.884,-110.635) v1@379.011,-110.635 ; 374.581,-110.316 ccw(c375.351,-109.546) 375.351,-110.635 ; 374.758,278.008 cw(c373.657,276.907) 375.214,276.907 ; 374.796,-103.613 cw(c373.662,-104.746) 375.265,-104.746 cw(c376.868,-104.746) 375.735,-103.613 ; 374.815,-102.655 ccw(c373.864,-101.626) v1(375.265,-101.626) ccw(c376.666,-101.626) 375.716,-102.655 ; 375.045,-143.142 ccw(c374.735,-142.832) 375.173,-142.832 ccw(c375.611,-142.832) 375.302,-143.142 ; 375.123,-138.53 ccw(c374.525,-137.932) 375.37,-137.932 ccw(c376.215,-137.932) 375.618,-138.53 ; 375.173,-143.27 375.173,-141.599 375.37,-141.402 ; 375.173,-142.847 cw(c376.69,-142.847) 375.618,-141.775 ; 375.265,-105.311 375.265,-103.143 v1(375.265,-101.626) ; 375.265,-104.603 ccw(c376.446,-104.603) 375.611,-105.438 ; 375.305,-138.951 cw(c375.722,-139.435) 376.173,-138.983 ; 375.328,276.907 374.275,277.96 374.035,277.96 ; 375.329,-117.047 ccw(c373.783,-115.501) 375.97,-115.501 ; 375.339,276.03 375.339,276.157 375.339,277.427 374.805,277.96 374.035,277.96 ; 375.339,280.359 374.591,279.611 374.416,279.611 ; 375.339,281.618 375.339,279.967 ; 375.36,-138.928 cw(c375.504,-140.386) 376.54,-139.35 ; 375.37,-137.602 cw(c376.021,-137.602) 375.561,-137.142 ; 375.457,-117.213 375.97,-116.701 375.97,-114.349 ; 375.457,-116.994 ccw(c375.457,-116.464) 375.832,-116.839 ; 375.471,-137.013 375.37,-137.114 375.37,-138.902 376.092,-138.902 ; 375.599,-139.292 cw(c376.039,-139.803) 376.516,-139.326 ; 375.645,-139.119 cw(c376.092,-139.472) 376.092,-138.902 ; 375.645,-138.685 ccw(c376.092,-138.332) 376.092,-138.902 ; 375.647,-117.365 ccw(c374.869,-116.587) 375.97,-116.587 ; 375.773,-135.164 ccw(c375.464,-134.854) 375.902,-134.854 ccw(c376.34,-134.854) 376.03,-135.164 ; 375.773,-133.777 cw(c375.464,-134.086) 375.902,-134.086 cw(c376.34,-134.086) 376.03,-133.777 ; 375.902,-133.648 375.902,-135.254 377.679,-135.254 377.683,-135.258 ; 375.97,-110.635 375.97,-108.253 ; 376.03,-135.421 cw(c376.432,-135.822) 376.432,-135.254 ; 376.116,-98.413 cw(c376.636,-98.933) 376.636,-98.197 ; 376.15,-173.745 ccw(c375.471,-172.883) 376.568,-172.883 ; 376.277,-97.735 ccw(c376.916,-97.524) 376.916,-98.197 ; v1(376.321,318.84) 376.321,319.621 376.545,319.845 376.545,320.544 376.863,320.861 378.006,320.861 378.196,321.052 378.196,322.004 ; v1@376.321,318.957 cw(c377.395,318.957) 376.635,319.717 ; 376.354,286.468 cw(c376.044,286.159) 376.482,286.159 cw(c376.92,286.159) 376.61,286.468 ; 376.417,319.973 ccw(c376.107,320.283) 376.545,320.283 ccw(c376.983,320.283) 376.674,319.973 ; v1(376.482,285.682) 376.482,286.635 ; 376.545,317.479 376.545,317.686 ; 376.568,-174.625 376.568,-172.883 ; 376.609,276.03 376.609,267.013 376.609,264.727 377.117,264.219 382.451,264.219 383.085,263.585 ; v1@376.701,-139.687 cw(c376.406,-139.983) 376.823,-139.983 ; 376.877,-117.047 ccw(c376.003,-116.173) v1@377.24,-116.173 ; 376.963,-132.313 ccw(c376.491,-131.841) 377.047,-131.47 ; 376.986,-173.745 cw(c377.665,-172.883) 376.568,-172.883 ; 377.006,-117.213 377.24,-116.98 v1(377.24,-116.104) 377.24,-114.349 ; 377.044,-105.438 ccw(c376.734,-105.129) 377.172,-105.129 ccw(c377.61,-105.129) 377.3,-105.438 ; 377.08,-135.254 cw(c377.08,-135.822) 377.482,-135.421 ; 377.082,-105.695 cw(c376.701,-106.076) 377.24,-106.076 ; 377.172,-105.567 377.172,-98.453 376.916,-98.197 ; 377.24,-108.253 377.24,-105.634 ; v1@377.309,-116.001 378.51,-116.001 378.51,-114.349 ; v1@377.328,-116.192 cw(c377.79,-116.654) 377.79,-116.001 ; 377.418,-133.964 cw(c376.778,-134.604) 377.683,-134.604 cw(c378.588,-134.604) 377.948,-133.964 ; 377.558,-135.164 ccw(c377.257,-134.863) 377.683,-134.863 ; 377.649,-135.292 377.683,-135.258 ; 377.683,-134.846 ccw(c378.133,-134.846) 377.815,-135.164 ; 377.683,-133.757 377.683,-135.258 ; 377.854,290.428 cw(c377.566,290.13) 377.98,290.13 ; 377.879,276.03 377.879,267.663 377.879,265.377 378.387,264.869 389.04,264.869 390.197,263.712 ; 377.98,290.128 cw(c378.329,290.128) 378.125,290.411 ; 377.98,290.558 377.98,290.13 ; 378.068,321.876 cw(c377.758,321.566) 378.196,321.566 cw(c378.634,321.566) 378.325,321.876 ; 378.107,290.428 ccw(c378.395,290.13) 377.98,290.13 ; 378.2,290.554 ccw(c379.662,290.517) v1@378.628,289.483 ; 378.377,-99.657 ccw(c376.757,-98.038) 379.046,-97.964 ; 378.432,323.626 cw(c378.432,322.636) 379.132,323.336 ; 378.432,324.036 v1@379.623,322.845 ; 378.554,-117.213 380.103,-117.213 ; 378.568,-105.438 ccw(c378.258,-105.129) 378.696,-105.129 ccw(c379.134,-105.129) 378.824,-105.438 ; 378.682,-117.342 cw(c378.992,-117.651) 378.992,-117.213 cw(c378.992,-116.775) 378.682,-117.085 ; 378.696,-105.567 378.696,-104.803 378.186,-104.293 378.186,-99.848 380.091,-97.943 ; v1(378.734,292.17) 379.631,291.273 379.631,290.558 ; 378.778,323.973 ccw(c379.462,323.973) 378.978,323.489 ; v1(378.861,289.249) 377.98,290.13 ; v1(378.861,316.554) 383.687,316.554 384.356,317.223 v1(384.356,319.475) 384.356,320.417 ; 379.111,-98.923 ccw(c378.181,-97.992) 379.496,-97.95 ; 379.149,276.03 379.149,268.313 379.149,266.027 379.657,265.519 395.629,265.519 397.316,263.832 ; 379.227,-98.807 cw(c379.71,-99.29) 379.71,-98.607 ; 379.294,-97.426 ccw(c378.383,-96.292) 379.837,-96.292 ; 379.3,-135.292 379.689,-135.292 381.283,-133.698 381.283,-131.517 381.515,-131.285 ; 379.338,-135.111 ccw(c379.338,-133.825) 380.247,-134.734 ; 379.475,322.993 cw(c379.146,322.664) v1@379.611,322.664 ; 379.503,290.686 ccw(c379.193,290.996) 379.631,290.996 ccw(c380.069,290.996) 379.76,290.686 ; 379.674,-102.626 ccw(c378.968,-101.753) v1(380.091,-101.753) ccw(c381.214,-101.753) 380.508,-102.626 ; 379.78,-117.155 379.78,-114.349 ; 379.78,-115.958 ccw(c381.32,-115.958) 380.231,-117.047 ; 379.78,-112.057 v1(379.78,-109.754) ; 379.837,-96.647 ccw(c381.007,-96.647) 380.18,-97.473 ; 379.974,-117.342 ccw(c379.665,-117.651) 379.665,-117.213 ccw(c379.665,-116.775) 379.974,-117.085 ; 380.091,-103.143 v1(380.091,-101.753) ; 380.257,-105.695 cw(c378.817,-107.135) 380.853,-107.135 ; 380.301,-134.68 ccw(c379.32,-133.698) 380.708,-133.698 ; 380.347,-105.567 380.853,-106.073 380.853,-110.389 v1(380.599,-110.643) ; 380.374,-105.748 cw(c380.344,-106.256) 380.853,-106.256 ; 380.419,276.03 380.419,269.09 380.419,266.804 381.054,266.169 403.338,266.169 404.428,265.08 404.428,261.97 ; v1@380.511,-110.555 ccw(c379.684,-109.728) 380.853,-109.728 ; 380.566,-105.567 ccw(c381.096,-105.567) 380.722,-105.941 ; 380.575,-105.377 cw(c379.903,-106.048) 380.853,-106.048 ; 380.673,319.464 380.673,319.147 382.133,317.686 ; 381.018,-133.433 ccw(c380.378,-132.793) 381.283,-132.793 ccw(c382.188,-132.793) 381.548,-133.433 ; 381.019,319.401 ccw(c382.469,319.401) 381.444,318.375 ; 381.117,-131.556 cw(c380.717,-131.956) 381.283,-131.956 ; 381.283,-133.076 cw(c383.433,-133.076) 381.913,-131.556 ; 381.283,-131.99 cw(c382.346,-131.99) 381.594,-131.238 ; 381.413,-71.776 381.579,-71.942 387.573,-71.942 ; 381.673,321.964 381.776,322.068 ; 381.673,326.126 cw(c381.673,325.136) 382.373,325.836 cw(c383.073,326.536) 382.083,326.536 ; 381.673,326.536 382.891,325.317 384.038,325.317 ; 381.682,-72.057 cw(c381.961,-72.336) 381.961,-71.942 ; 381.682,-71.801 ccw(c382.022,-71.461) 382.022,-71.942 ; 381.689,276.03 381.689,269.934 381.689,267.648 382.518,266.819 410.054,266.819 411.667,265.207 411.667,261.97 ; 381.759,318.061 cw(c381.384,317.686) 381.914,317.686 ; 381.928,338.398 388.64,338.398 390.545,338.398 ; 381.928,340.938 392.831,340.938 393.466,340.303 393.466,338.652 ; 382.3,338.027 cw(c383.196,337.131) 383.196,338.398 cw(c383.196,339.666) 382.3,338.77 ; 382.3,340.567 cw(c383.196,339.671) 383.196,340.938 cw(c383.196,342.206) 382.3,341.31 ; 382.623,324.036 382.623,323.461 382.798,323.285 v1(383.56,323.285) ; 382.709,262.881 ccw(c382.238,263.585) 383.085,263.585 ; 382.798,333.289 cw(c382.798,332.3) 383.498,333 ; 382.798,333.699 384.356,332.142 384.356,326.651 ; 382.909,303.31 v1@382.909,309.315 ; 382.909,304.092 ccw(c383.78,304.092) 383.164,303.476 ; 383.085,261.97 383.085,263.585 ; 383.144,333.636 ccw(c383.828,333.636) 383.345,333.153 ; 383.236,-173.772 ccw(c382.332,-172.764) 383.687,-172.764 ; 383.243,325.317 cw(c383.243,323.926) 384.228,324.91 ; 383.46,262.881 cw(c383.932,263.585) 383.085,263.585 ; 383.687,-174.625 383.687,-172.763 ; 383.977,-75.196 ccw(c382.631,-76.106) v1@382.631,-74.482 ; 383.977,-73.768 cw(c382.631,-72.858) v1@382.631,-74.482 ; 384.138,-173.772 cw(c385.042,-172.764) 383.687,-172.764 ; 384.228,320.25 cw(c383.918,319.941) 384.356,319.941 cw(c384.794,319.941) 384.484,320.25 ; 384.228,326.817 ccw(c383.918,327.127) 384.356,327.127 ccw(c384.794,327.127) 384.484,326.817 ; 384.349,-74.944 ccw(c383.479,-75.533) 383.479,-74.482 ccw(c383.479,-73.431) 384.349,-74.02 ; 384.917,-74.482 v1@382.631,-74.482 ; 384.991,297.303 386.608,297.303 386.999,297.693 386.999,299.132 387.448,299.582 ; 385.119,297.174 cw(c385.429,296.865) 385.429,297.303 cw(c385.429,297.741) 385.119,297.431 ; 385.512,297.303 ccw(c385.512,299.055) 386.751,297.816 ; 386.297,338.398 ccw(c386.297,340.869) 388.043,339.122 ; 386.742,-72.773 ccw(c384.736,-74.779) 384.736,-71.942 ccw(c384.736,-69.105) 386.742,-71.111 ; 386.751,294.821 cw(c385.786,293.855) 387.151,293.855 ; 386.751,298.066 ccw(c386.154,298.663) 386.999,298.663 ccw(c387.844,298.663) 387.246,298.066 ; 386.999,295.193 387.151,295.041 387.151,293.325 387.151,292.539 387.337,292.352 390.071,292.352 390.452,292.733 390.452,296.963 v1(390.418,296.996) 389.721,297.693 ; 386.999,298.151 cw(c388.842,298.151) 387.539,299.454 ; 386.999,298.973 cw(c387.427,298.973) 387.415,299.401 ; 386.999,299.237 cw(c387.755,299.237) 387.22,299.772 ; 387.023,293.197 cw(c386.713,292.887) 387.151,292.887 cw(c387.589,292.887) 387.279,293.197 ; 387.023,293.454 ccw(c386.713,293.763) 387.151,293.763 ccw(c387.589,293.763) 387.279,293.454 ; 387.06,-72.455 ccw(c385.822,-73.692) 385.822,-71.942 ccw(c385.822,-70.192) 387.06,-71.429 ; 387.074,299.207 ccw(c386.699,299.582) 387.229,299.582 ; v1(387.226,326.19) 388.082,326.19 ; 387.383,338.398 ccw(c387.383,339.782) 388.362,338.804 ; 387.523,338.398 cw(c387.523,337.663) 388.043,338.183 ; 387.751,303.075 ccw(c387.441,303.385) 387.879,303.385 ccw(c388.317,303.385) 388.008,303.075 ; 387.879,302.947 387.879,303.602 388.259,303.981 390.291,303.981 391.144,304.834 391.144,305.31 ; 387.954,326.061 ccw(c387.644,325.752) 387.644,326.19 ccw(c387.644,326.628) 387.954,326.318 ; 388.082,326.317 388.437,325.961 v1(392.513,325.961) v1@392.64,325.961 ; 388.21,326.28 ccw(c388.98,327.049) 388.98,325.961 ; 388.424,332.983 cw(c387.291,331.849) 388.894,331.849 cw(c390.497,331.849) 389.363,332.983 ; 388.443,333.94 ccw(c387.493,334.969) v1(388.894,334.969) ccw(c390.295,334.969) 389.344,333.94 ; 388.674,293.454 ccw(c388.364,293.763) 388.802,293.763 ccw(c389.24,293.763) 388.93,293.454 ; 388.751,298.066 ccw(c388.154,298.663) 388.999,298.663 ccw(c389.844,298.663) 389.246,298.066 ; 388.802,293.325 388.802,294.997 388.999,295.193 ; 388.802,293.749 cw(c390.318,293.749) 389.246,294.821 ; 388.894,331.285 388.894,333.452 v1(388.894,334.969) ; 388.894,331.992 ccw(c390.075,331.992) 389.24,331.157 ; 388.933,297.644 cw(c389.351,297.161) 389.802,297.612 ; 388.958,319.548 ccw(c387.412,321.095) 389.598,321.095 ; 388.989,297.668 cw(c389.133,296.21) 390.169,297.246 ; 388.999,298.993 cw(c389.65,298.993) 389.19,299.454 ; 389.086,319.382 389.598,319.894 389.598,322.246 ; 389.086,319.602 ccw(c389.086,320.132) 389.461,319.757 ; 389.099,299.582 388.999,299.481 388.999,297.693 389.721,297.693 ; 389.227,297.303 cw(c389.668,296.793) 390.145,297.27 ; 389.273,297.476 cw(c389.721,297.123) 389.721,297.693 ; 389.273,297.91 ccw(c389.721,298.264) 389.721,297.693 ; 389.276,319.23 ccw(c388.498,320.008) 389.598,320.008 ; 389.402,301.431 ccw(c389.092,301.741) 389.53,301.741 ccw(c389.968,301.741) 389.659,301.431 ; 389.402,302.819 cw(c389.092,302.509) 389.53,302.509 cw(c389.968,302.509) 389.659,302.819 ; 389.53,302.947 389.53,301.341 391.308,301.341 391.312,301.338 ; 389.598,325.961 389.598,328.342 ; 389.659,301.175 cw(c390.06,300.773) 390.06,301.341 ; 389.744,338.183 cw(c390.265,337.663) 390.265,338.398 ; 389.779,262.851 ccw(c389.1,263.712) 390.197,263.712 ; 389.905,338.861 ccw(c390.545,339.072) 390.545,338.398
